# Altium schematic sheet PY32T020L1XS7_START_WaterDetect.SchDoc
size A3
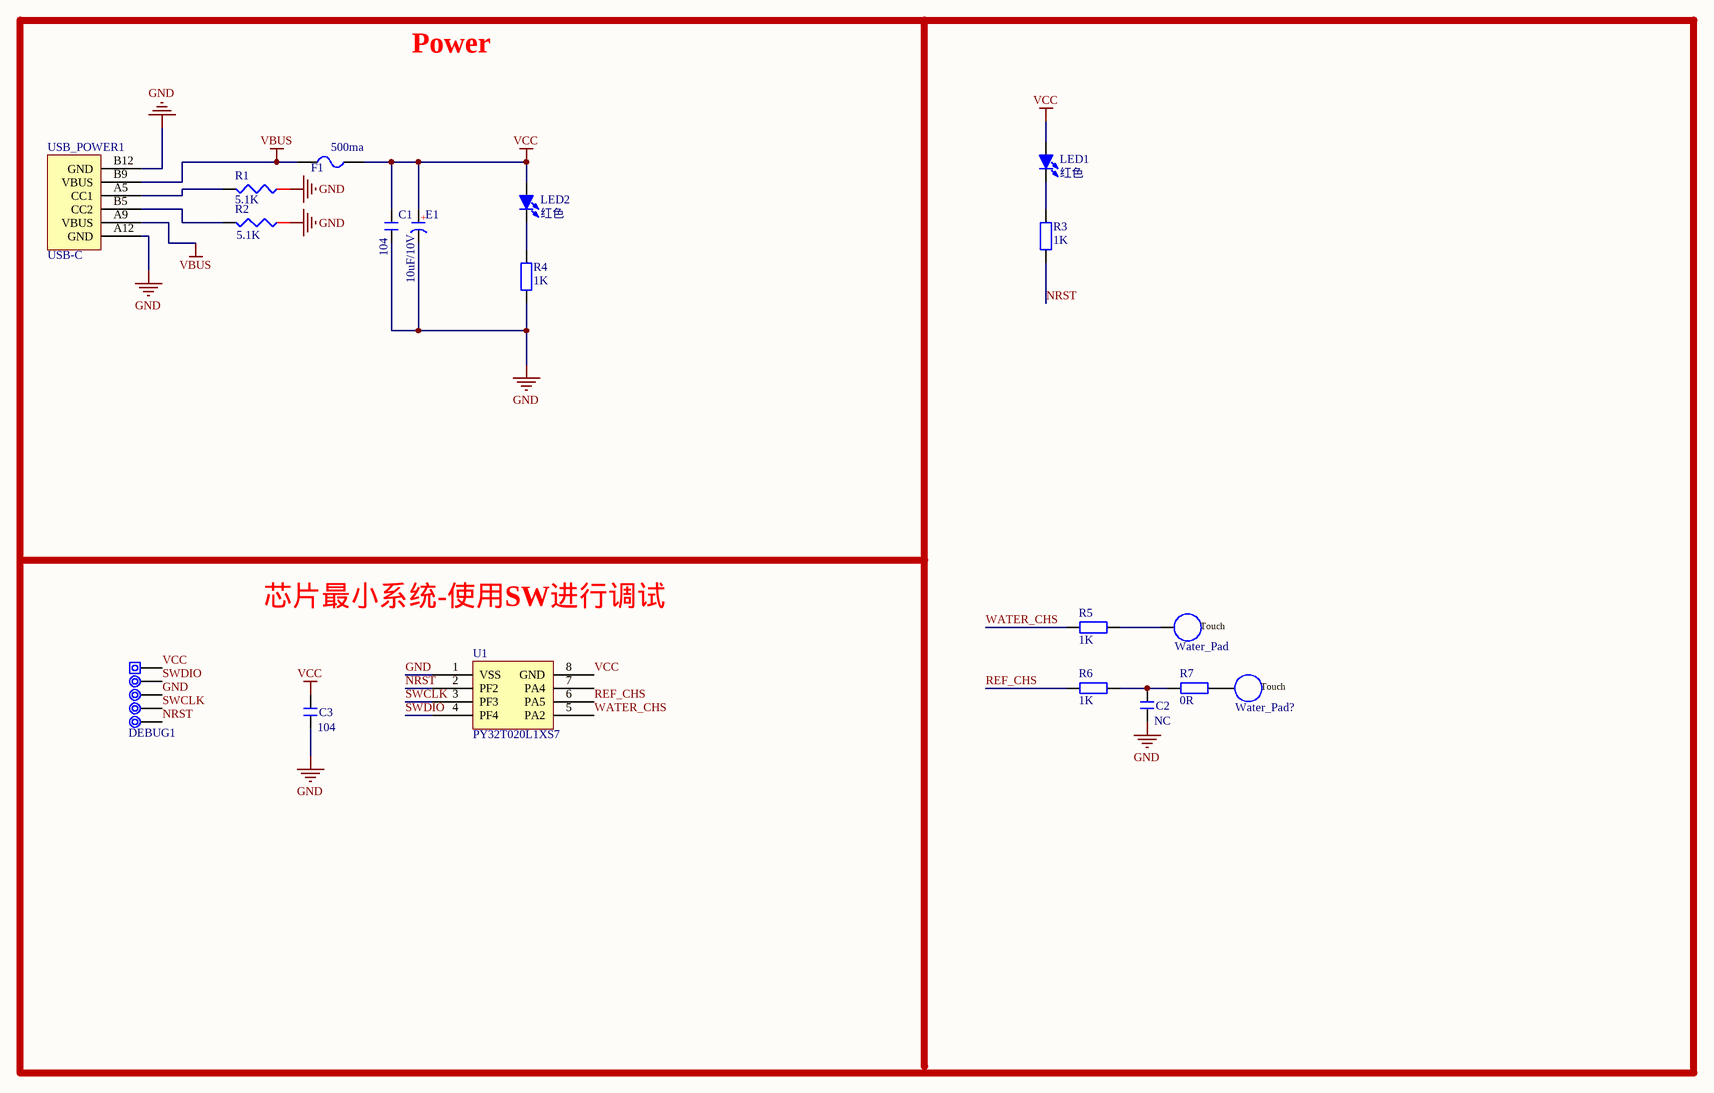
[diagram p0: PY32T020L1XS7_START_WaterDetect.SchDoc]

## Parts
C1  104  [C 0603_L]
C2  NC  [C 0603_L]
C3  104  [C 0603_L]
DEBUG1  ISP  [ISP_DIP_2.54_5P]  (value not drawn)
E1  10uF/10V  [C 0805_L]
F1  500ma  [FU 0805]
LED1  红色  [LED 0805R]
LED2  红色  [LED 0805R]
R1  5.1K  [R 0603_L]
R2  5.1K  [R 0603_L]
R3  1K  [R 0603_L]
R4  1K  [R 0603_L]
R5  1K  [R 0603_L]
R6  1K  [R 0603_L]
R7  0R  [R 0603_L]
U1  PY32T020L1XS7  [SOP8_N]
USB_POWER1  USB-C  [USB-C/S_C]
Water_Pad  Touch 10X10mm  [Touch-10X10mm]  (value not drawn)
Water_Pad?  Touch 10X10mm  [Touch-10X10mm]  (value not drawn)

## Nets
GND: C1.1 C2.1 C3.1 DEBUG1.3 E1.2(K) R1.1 R2.1 R4.1 U1.1(VSS) USB_POWER1.A12(GND) USB_POWER1.B12(GND)
VBUS: F1.1 USB_POWER1.A9(VBUS) USB_POWER1.B9(VBUS)
VCC: C1.2 C3.2 DEBUG1.1 E1.1(A) F1.2 LED1.1(A) LED2.1(A) U1.8(GND)
NRST: DEBUG1.5 R3.1 U1.2(PF2)
REF_CHS: R6.2 U1.6(PA5)
SWCLK: DEBUG1.4 U1.3(PF3)
SWDIO: DEBUG1.2 U1.4(PF4)
WATER_CHS: R5.2 U1.5(PA2)
NetC2_2: C2.2 R6.1 R7.2
NetLED1_2: LED1.2(K) R3.2
NetLED2_2: LED2.2(K) R4.2
NetR1_2: R1.2 USB_POWER1.A5(CC1)
NetR2_2: R2.2 USB_POWER1.B5(CC2)
NetR5_1: R5.1 Water_Pad.Touch
NetR7_1: R7.1 Water_Pad?.Touch

Not connected (* = marked no-connect by the designer): U1 7(PA4)

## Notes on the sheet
- Power
- 芯片最小系统-使用SW进行调试

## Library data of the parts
C1-C3 = C: 无极性贴片电容; 版权归属: 源创客; 材质: X7R
DEBUG1 = ISP_5Pin: 程序下载端口; 版权归属: 源创客
E1 = C-CM: 贴片电解电容; 版权归属: 源创客
F1 = FU: 贴片保险丝; 版权归属: 源创客
LED1 LED2 = LED-SMD: 贴片LED; 版权归属: 源创客
R1 R2 = R
R3-R7 = R: 贴片电阻; 版权归属: 源创客
USB_POWER1 = USB-C_6P/S: USB-C_6P型母接口; BOM名称: USB-C型母接口; 版权归属: 源创客
Water_Pad Water_Pad? = Touch-1P: 触控焊盘; 版权归属: 源创客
